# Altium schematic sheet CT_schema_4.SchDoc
size 273 x 214 mm
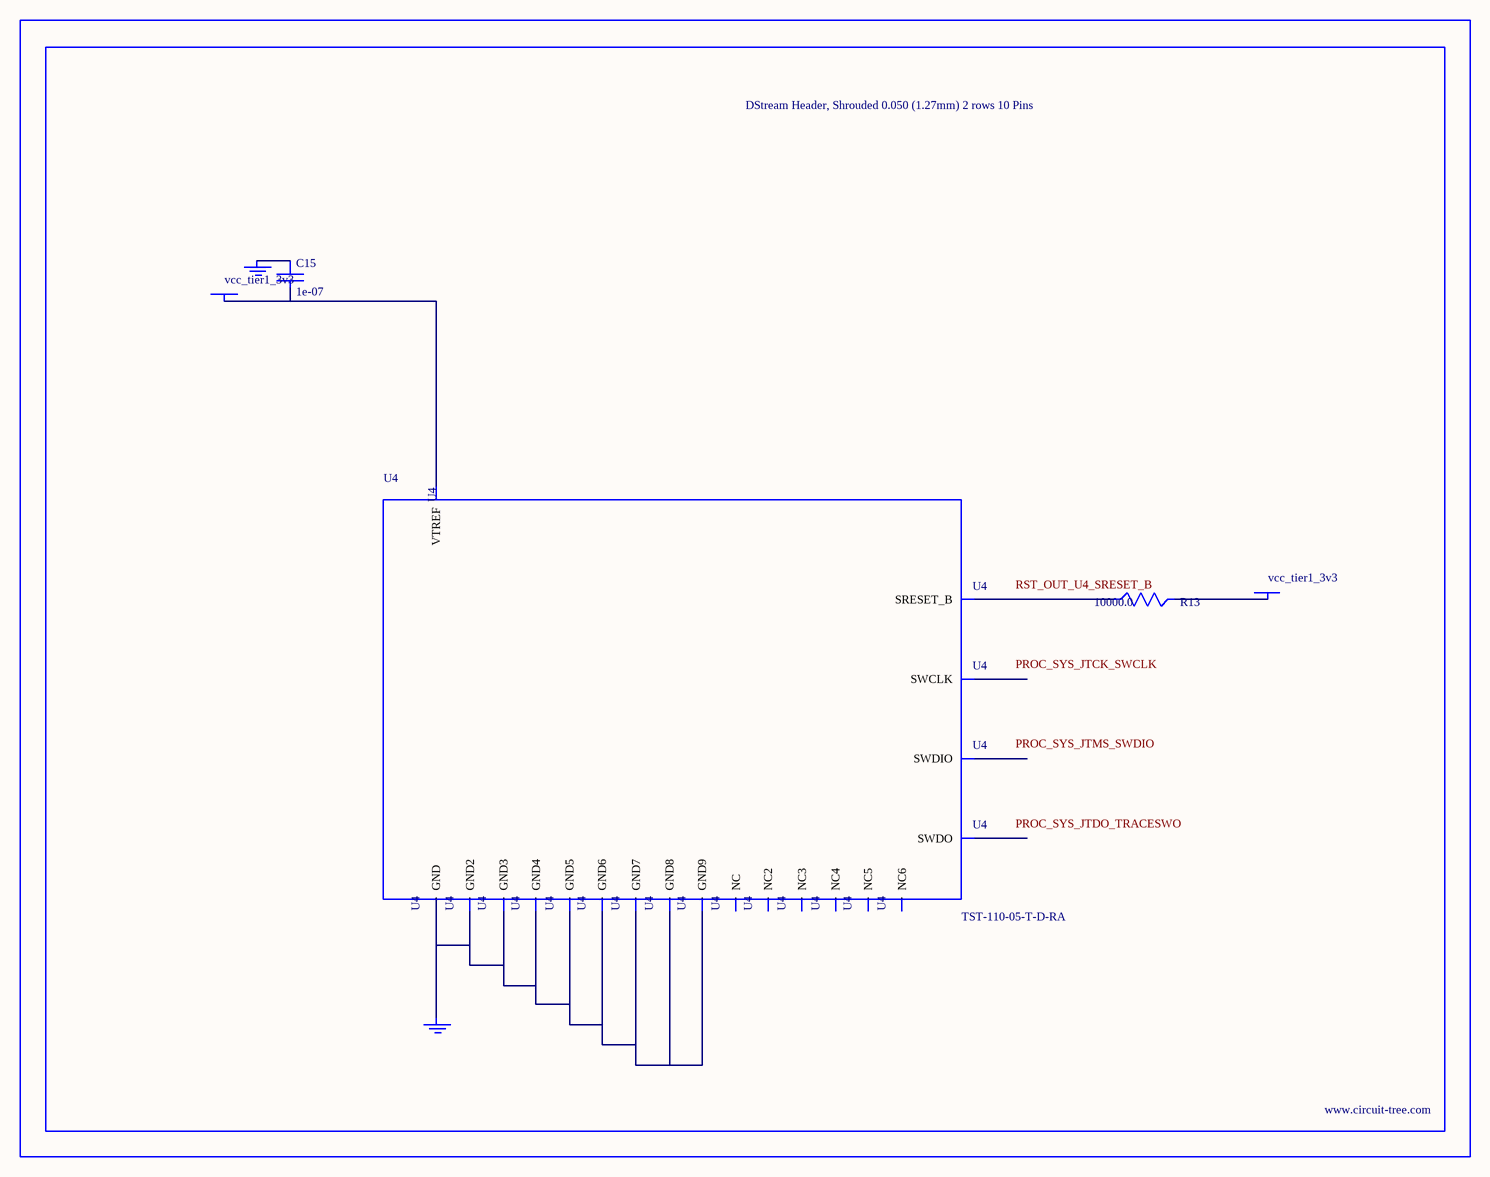
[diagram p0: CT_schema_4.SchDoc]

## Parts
BORDER3  (no value)
C15  1e-07  [C0402]
GND_INSTANCE_3_0  (no value)
GND_INSTANCE_3_1  (no value)
POWER_INSTANCE_3_0  vcc_tier1_3v3
POWER_INSTANCE_3_1  vcc_tier1_3v3
R13  10000.0  [R0603]
U4  TST-110-05-T-D-RA  [TST-110-05-T-D-RA]

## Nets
NetC15_1: C15.1 GND_INSTANCE_3_0.0(GND)
NetC15_2: C15.2 POWER_INSTANCE_3_0.0(PWR) U4.1(VTREF)
NetGND_INSTANCE_3_1_0: GND_INSTANCE_3_1.0(GND) U4.4(GND) U4.6(GND2) U4.8(GND3) U4.10(GND4) U4.12(GND5) U4.14(GND6) U4.16(GND7) U4.18(GND8) U4.20(GND9)
NetPOWER_INSTANCE_3_1_0: POWER_INSTANCE_3_1.0(PWR) R13.2
NetR13_1: R13.1 U4.15(SRESET_B)

Not connected (* = marked no-connect by the designer): U4 2(NC) 3(NC2) 5(NC3) 7(SWDIO) 9(SWCLK) 11(NC4) 13(SWDO) 17(NC5) 19(NC6)

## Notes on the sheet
- Labels drawn without touching a wire or pin: PROC_SYS_JTCK_SWCLK, PROC_SYS_JTDO_TRACESWO, PROC_SYS_JTMS_SWDIO, RST_OUT_U4_SRESET_B

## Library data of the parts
BORDER3 = BORDER_PAGE3
C15 = C0402C104K3RACTU
GND_INSTANCE_3_0 GND_INSTANCE_3_1 = GND
POWER_INSTANCE_3_0 POWER_INSTANCE_3_1 = PWR
R13 = RC0603JR-0710KL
